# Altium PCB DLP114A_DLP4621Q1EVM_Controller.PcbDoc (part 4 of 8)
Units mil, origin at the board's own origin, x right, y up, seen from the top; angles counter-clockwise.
Board outline 4803.15 x 2598.43 mil, 14 copper layers (Top Layer, GND 1, SIGNAL 1, GND 2, SIGNAL 2, PWR SPLIT PLANE 1, GND 3, GND 4, PWR SPLIT PLANE 2, SIGNAL 3, GND 5, SIGNAL 4, GND 6, Bottom Layer), stack 91.4 mil thick; 489 components, 394 nets, 1925 pads, 1273 vias.
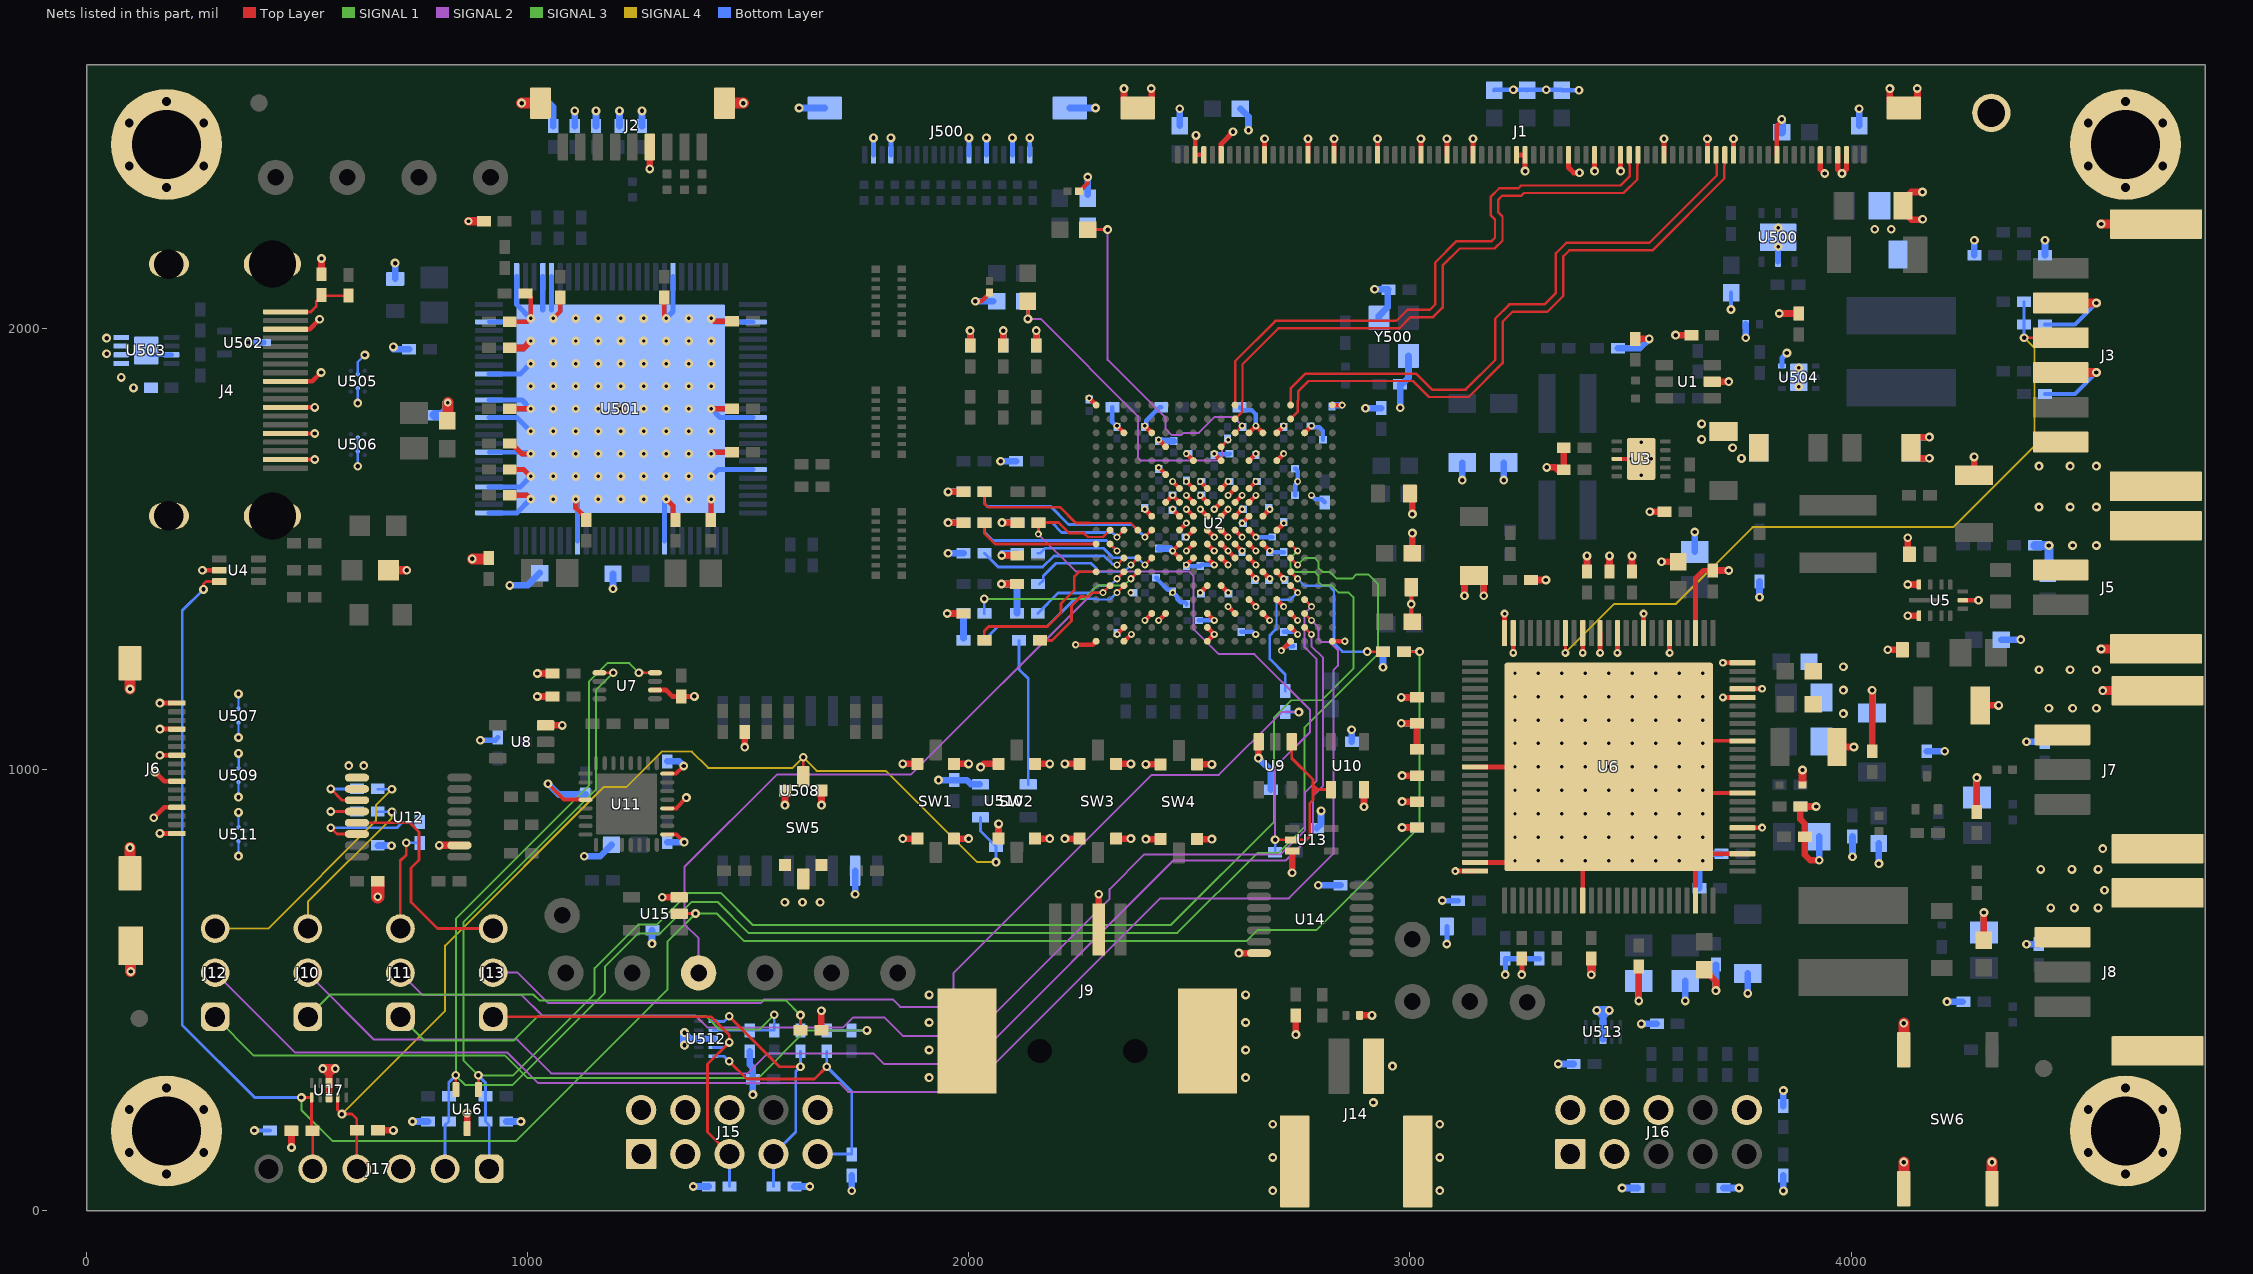
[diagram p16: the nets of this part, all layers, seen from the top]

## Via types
v1: diameter 20, hole 10, Top Layer to Bottom Layer, tented top, 716 vias
v2: diameter 16, hole 8, Top Layer to Bottom Layer, 234 vias
v3: diameter 19.68, hole 7.87, Top Layer to Bottom Layer, 170 vias
v4: diameter 18, hole 8, Top Layer to Bottom Layer, tented top, 78 vias
v5: diameter 18, hole 8, Top Layer to Bottom Layer, tented bottom, 51 vias
v6: diameter 39.37, hole 19.68, Top Layer to Bottom Layer, 24 vias

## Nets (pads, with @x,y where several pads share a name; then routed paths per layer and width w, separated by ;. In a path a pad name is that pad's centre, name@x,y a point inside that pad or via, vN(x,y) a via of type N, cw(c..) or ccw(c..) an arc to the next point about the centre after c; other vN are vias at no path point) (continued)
GND: C1.2 C2.2 C3.2 C6.2 C7.2 C8.2 C9.2 C10.2 C11.2 C12.2 C13.2 C14.2 C15.2 C16.2 C17.2 C18.2 C19.2 C20.2 C21.2 C22.2 C23.2 C24.1 C25.2 C27.2 C28.2 C29.2 C30.2 C31.1 C32.2 C33.2 C34.2 C35.1 C36.2 C37.1 C39.2 C40.2 C41.2 C42.2 C43.2 C44.2 C45.2 C46.2 C47.2 C48.2 C49.2 C50.2 C51.1 C52.2 C53.2 C54.2 C55.2 C56.1 C57.2 C58.2 C59.2 C500.2 C501.1 C502.2 C503.2 C504.2 C505.2 C506.2 C507.2 C508.2 C509.2 C510.2 C511.2 C512.2 C513.2 C514.2 C515.2 C516.2 C517.1 C518.2 C519.1 C520.2 C521.2 C522.2 C523.2 C524.2 C525.2 C526.2 C527.2 C528.2 C529.2 C530.2 C531.2 C532.2 C535.2 C536.2 C537.2 C538.2 C539.2 C540.2 C541.2 C542.2 C543.2 C544.2 C545.2 C546.2 C547.2 C548.2 C549.2 C550.2 C551.2 C552.2 C553.2 C554.2 C555.2 C556.2 C557.2 C558.2 C559.2 C560.2 C562.2 C563.2 C564.2 C565.2 C566.2 C567.2 C568.2 C569.2 C570.2 C571.2 C572.2 C573.2 C574.2 C575.2 C576.2 C577.2 C578.2 C579.2 C580.2 C581.2 C582.2 C583.2 C584.2 C585.2 C586.2 C587.2 C588.2 C589.2 C590.2 C591.2 C592.2 C593.2 C594.2 C595.2 C596.2 C597.2 C598.2 C599.2 C600.2 C601.2 C602.2 C603.2 C604.2 C605.2 C606.1 C607.2 C608.2 C609.2 C610.2 C612.1 C613.2 C614.2 C615.2 C616.2 C617.2 C618.2 C619.2 C620.2 C621.2 C622.2 C623.2 C624.2 C625.2 C626.2 C627.2 C628.2 D3.2 D5.2 J1.3 J1.4 J1.6 J1.11 J1.16 J1.19 J1.24 J1.29 J1.32 J1.35 J1.40 J1.41 J1.46 J1.49 J1.52 J1.57 J1.62 J1.65 J1.70 J1.75 J1.77 J1.78 J1.81 J1.82 J2.6 J2.10 J2.11 J3.1 J3.3 J3.5 J3.7 J3.8 J4.2 J4.5 J4.8 J4.11 J4.17 J4.20 J4.21 J4.22 J4.23 J5.2 J5.3 J5.4 J6.1 J6.4 J6.7 J6.10 J6.13 J6.16 J6.17 J6.18 J7.3 J7.MP1 J7.MP2 J8.3 J8.MP1 J8.MP2 J9.4 J9.5 J9.6 J14.2 J14.3 J14.4 J15.1 J15.2 J15.3 J15.4 J15.6 J15.10 J16.1 J16.2 J16.3 J16.4 J16.6 J16.10 J17.3 J500.2 J500.4 J500.13 J500.15 J500.18 J500.20 J500.21 J500.22 L513.1 L517.1 MH1.1 MH2.1 MH3.1 MH4.1 R3.1 R4.1 R5.1 R6.1 R7.1 R8.1 R13.1 R16.1 R18.1 R21.1 R22.1 R23.1 R26.1 R27.1 R28.1 R29.1 R30.1 R32.1 R33.1 R35.1 R40.1 R41.1 R47.1 R50.1 R52.1 R54.1 R61.1 R63.1 R65.1 R510.1 R511.1 R512.1 R514.1 R515.2 R525.1 R526.1 R527.1 R528.1 R529.1 R531.1 R533.1 R536.1 R537.1 R541.1 R542.1 R543.1 R544.1 R545.1 R547.1 R548.1 R550.1 R551.1 R559.1 R562.1 R565.1 R569.1 R573.1 R574.1 R575.1 R576.1 R578.1 R579.1 R584.1 R591.1 SW1.3 SW1.4 SW1.5 SW1.6 SW2.3 SW2.4 SW2.5 SW2.6 SW3.3 SW3.4 SW3.5 SW3.6 SW4.3 SW4.4 SW4.5 SW4.6 SW5.2 SW5.3 SW5.4 SW5.5 SW5.6 SW6.3 SW6.4 SW6.5 TP16.1 TP17.1 U1.2 U2.A1 U2.A18 U2.C3 U2.C5 U2.C12 U2.C13 U2.C14 U2.C16 U2.D6 U2.E8 U2.E10 U2.E12 U2.E14 U2.F6 U2.G7 U2.G8 U2.G9 U2.G10 U2.G11 U2.G12 U2.H6 U2.H7 U2.H8 U2.H9 U2.H10 U2.H11 U2.H12 U2.J5 U2.J7 U2.J8 U2.J9 U2.J10 U2.J11 U2.J12 U2.J13 U2.K7 U2.K8 U2.K9 U2.K10 U2.K11 U2.K12 U2.K14 U2.L7 U2.L8 U2.L9 U2.L10 U2.L11 U2.L12 U2.L13 U2.M7 U2.M8 U2.M9 U2.M10 U2.M11 U2.M12 U2.N12 U2.N13 U2.N14 U2.P9 U2.P10 U2.R12 U2.R14 U2.T5 U2.T6 U2.T9 U2.T11 U2.T13 U2.T15 U2.U3 U2.U9 U2.U15 U2.V1 U2.V3 U2.V9 U2.V15 U2.V18 U3.8 U3.11 U4.2 U5.1 U5.6 U5.11 U6.13 U6.24 U6.25 U6.35 U6.48 U6.53 U6.56 U6.60 U6.66 U6.71 U6.72 U6.75 U6.78 U6.81 U6.84 U6.87 U6.89 U6.91 U6.99 U6.100 U6.101 U7.2 U8.3 U9.3 U10.3 U11.4 U11.17 U11.20 U11.24 U12.2 U12.9 U12.10 U13.3 U14.7 U15.3 U16.3 U17.3@549.37,257.02 U17.8@549.37,289.89 U500.2 U500.7@3834.53,2206.85 U501.1 U501.4 U501.5 U501.19 U501.28 U501.39 U501.45 U501.58 U501.68 U501.76 U501.79 U501.83 U501.87 U501.89 U501.92 U501.98 U501.101 U502.3 U503.1 U503.2 U503.3 U503.4 U503.7 U503.9 U504.3 U504.7@3881.47,1889.67 U505.B1 U505.B2 U506.B1 U506.B2 U507.B1 U507.B2 U508.10 U509.B1 U509.B2 U510.3 U511.B1 U511.B2 U512.3@1420.73,389.93 U512.8@1387.86,389.93 U513.3@3437.55,388.98 U513.8@3437.55,421.85 Y500.2 Y500.4 | length 20175.6
  Top Layer w8: v3(3663.27,1059.47) 3669.18,1065.37 U6.66@3753.82,1065.37
  Top Layer w9: v1(1045.91,968.22) 1082.15,931.98 U11.4@1130.85,931.98 ; U11.17@1316.13,853.24 1336.95,853.24 v1(1354.41,835.78) ; U11.24@1316.13,991.03 1336.5,991.03 v1(1353.83,1008.36) ; U11.20@1316.31,912.3 1336.73,912.3 ; 1336.54,912.29 v1(1359.82,936.68) ; U3.8@3468.87,1704.49 v3(3501.35,1704.49) ; v3(3663.27,953.17) 3676.12,953.17 3682.03,947.26 U6.60@3753.82,947.26
  Top Layer w9.84: U5.6@4253.1,1384.35 v1(4288.81,1384.35)
  Top Layer w10: v1(262.46,1452.14) U4.2@300.88,1452.14 ; J4.2@451.18,1703.2 v1(517.36,1703.2) ; J4.5@451.18,1762.26 v1(517.36,1762.26) ; J4.8@451.18,1821.31 v1(517.36,1821.31) ; J4.11@451.18,1880.37 511.47,1880.37 v1(531.47,1900.37) ; J4.17@451.18,1998.48 505.65,1998.48 v1(528.18,2021.02) ; C11.2@959.35,2015.17 998.72,2015.17 v3(1006.59,2023.04) 1006.59,2071.86 998.91,2079.54 R3.1@994.97,2079.54 ; v3(1057.77,2023.04) 1073.52,2038.79 C7.2@1073.52,2070.28 ; C8.2@1309.74,2070.28 1309.74,2026.98 v3(1313.68,2023.04) ; v1(2014.75,2062.09) 2028.43,2062.09 2046.98,2080.64 C9.2@2046.98,2081.43 ; v2(2241.87,1283.28) 2280.68,1283.28 U2.V1@2288.57,1291.17 ; C1.2@2250.12,2311.38 2250.91,2311.38 2269.46,2329.93 v1(2269.46,2343.61) ; v2(2272.83,1842.35) U2.A1@2288.57,1826.6 ; v2(2335.82,1779.36) U2.C3@2351.57,1763.61 ; v2(2336.02,1306.9) 2336.02,1307.01 2351.57,1322.55 U2.U3@2351.57,1322.67 ; U2.V3@2351.57,1291.17 2352.34,1291.17 2367.73,1306.55 v2(2368.51,1306.55) ; v2(2398.81,1338.42) U2.T5@2414.56,1354.16 ; v2(2398.81,1590.38) U2.J5@2414.56,1574.64 ; v2(2398.81,1779.36) U2.C5@2414.56,1763.61 ; v2(2430.31,1338.42) U2.T6@2446.05,1354.16 ; v2(2430.31,1684.87) U2.F6@2446.05,1669.12 ; v2(2430.31,1747.86) U2.D6@2446.05,1732.12 ; U2.H6@2446.05,1606.13 v2(2461.8,1621.88) U2.H7@2477.55,1606.13 ; v2(2461.8,1590.38) U2.J7@2477.55,1574.64 ; v2(2461.8,1653.38) U2.G7@2477.55,1637.63 ; U2.M7@2477.55,1480.15 v2(2461.8,1495.9) U2.L7@2477.55,1511.64 ; U2.K7@2477.55,1543.14 v2(2493.3,1558.89) ; v2(2493.3,1464.4) U2.M8@2509.05,1480.15 ; v2(2493.3,1495.9) U2.L8@2509.05,1511.64 ; v2(2493.3,1527.39) U2.K8@2509.05,1543.14 ; v2(2493.3,1590.38) U2.J8@2509.05,1574.64 ; v2(2493.3,1621.88) U2.H8@2509.05,1606.13 ; v2(2493.3,1653.38) U2.G8@2509.05,1637.63 ; v2(2493.3,1716.37) U2.E8@2509.05,1700.62 ; J1.78@2512.91,2393.7 J1.77@2532.6,2393.7 ; J1.78@2513.25,2402.66 2513.25,2436.38 v1(2514.92,2438.05) ; v2(2524.79,1401.41) U2.P9@2540.54,1417.16 ; v2(2524.79,1590.38) U2.J9@2540.54,1574.64 ; v2(2524.79,1621.88) U2.H9@2540.54,1606.13 ; v2(2524.79,1653.38) U2.G9@2540.54,1637.63 ; U2.V9@2540.55,1291.17 v2(2556.29,1306.9) U2.U9@2540.54,1322.67 ; U2.T9@2540.54,1354.16 v2(2556.29,1338.42) ; U2.M9@2540.54,1480.15 v2(2556.29,1464.4) ; U2.L9@2540.54,1511.64 v2(2556.29,1495.9) ; U2.K9@2540.54,1543.14 v2(2556.29,1527.39) ; v2(2556.29,1590.38) U2.H10@2572.04,1606.13 ; v2(2556.29,1716.37) U2.E10@2572.04,1700.62 ; U2.P10@2572.04,1417.16 v2(2587.79,1401.41) ; U2.M10@2572.04,1480.15 v2(2587.79,1464.4) ; U2.L10@2572.04,1511.64 v2(2587.79,1495.9) U2.M11@2603.53,1480.15 ; U2.K10@2572.04,1543.14 v2(2587.79,1527.39) ; U2.J10@2572.04,1574.64 v2(2587.79,1590.38) ; U2.G10@2572.04,1637.63 v2(2587.79,1653.38) ; v2(2587.79,1369.91) U2.T11@2603.53,1354.16 ; v2(2587.79,1621.88) U2.G11@2603.53,1637.63 ; U2.L11@2603.53,1511.64 v2(2619.28,1495.9) ; U2.K11@2603.53,1543.14 v2(2619.28,1527.39) ; U2.J11@2603.53,1574.64 v2(2619.28,1590.38) ; U2.H11@2603.53,1606.13 v2(2619.28,1621.88) ; v2(2619.28,1558.89) U2.J12@2635.03,1574.64 ; U2.R12@2635.03,1385.66 v2(2650.78,1369.91) ; U2.N12@2635.03,1448.65 v2(2650.78,1432.9) ; U2.M12@2635.03,1480.15 v2(2650.78,1464.4) ; U2.L12@2635.03,1511.64 v2(2650.78,1495.9) ; U2.K12@2635.03,1543.14 v2(2650.78,1527.39) ; U2.H12@2635.03,1606.13 v2(2650.78,1621.88) ; U2.G12@2635.03,1637.63 v2(2650.78,1653.38) ; U2.E12@2635.03,1700.62 v2(2650.78,1716.37) ; U2.C12@2635.03,1763.61 v2(2650.78,1779.36) U2.C13@2666.53,1763.61 ; U2.T13@2666.53,1354.16 2666.53,1353.93 2681.81,1338.65 v2(2681.81,1338.42) ; U2.N13@2666.53,1448.65 v2(2682.27,1432.9) ; U2.L13@2666.53,1511.64 v2(2682.27,1495.9) ; U2.J13@2666.53,1574.64 v2(2682.27,1590.38) ; U2.R14@2698.02,1385.66 v2(2713.77,1369.91) ; U2.N14@2698.02,1448.65 v2(2713.77,1432.9) ; U2.K14@2698.02,1543.14 v2(2713.77,1558.89) ; U2.E14@2698.02,1700.62 v2(2713.77,1716.37) ; U2.C14@2698.02,1763.61 v2(2713.77,1779.36) ; v2(2708.31,1269.96) U2.V15@2729.52,1291.17 ; U2.U15@2729.52,1322.67 v2(2745.27,1306.9) ; U2.T15@2729.52,1354.16 v2(2745.27,1338.42) ; U2.C16@2761.01,1763.61 v2(2776.76,1779.36) ; U2.A18@2824.01,1826.6 v2(2846.28,1826.6) ; U2.V18@2824.19,1291.17 v2(2852.54,1291.17) ; C35.1@3002.89,1413.65 v1(3002.89,1375.52) 3002.89,1337.38 C36.2@3005.35,1334.92 ; J1.11@3831.81,2393.7 3831.81,2460.49 3842.7,2471.38 v1(3842.7,2474.09)
  Top Layer w11: v1(152.34,891.13) 175.99,914.77 J6.13@204.72,914.77 ; v1(155.29,994.54) 176,973.83 J6.10@204.72,973.83 ; v1(166.04,855.72) J6.16@204.72,855.72 ; v1(166.04,1032.88) J6.7@204.72,1032.88 ; v1(166.04,1091.94) J6.4@204.72,1091.94 ; v1(166.04,1150.99) J6.1@204.72,1150.99 ; U7.2@1288.48,1180.54 1313.62,1180.54 1328.07,1166.09 C40.2@1348.1,1166.09 v1(1377.91,1166.09) ; v4(3103,770.1) U6.25@3147.52,770.1 ; U6.24@3147.52,789.78 3234.38,789.78 U6.101@3237.78,793.19 ; U6.13@3147.52,1006.32 v3(3238.08,1006.32) ; U6.100@3214.45,1309.47 v4(3214.45,1354) ; v4(3234.14,1264.94) U6.99@3234.14,1309.47 ; J1.41@3241.26,2393.7 J1.40@3260.94,2393.7 ; v3(3344.37,793.72) 3373.5,793.72 3391.62,775.6 U6.35@3391.62,703.17 ; v4(3391.62,1264.94) U6.91@3391.62,1309.47 ; v4(3430.99,1264.94) U6.89@3430.99,1309.47 ; v4(3470.36,1264.94) U6.87@3470.36,1309.47 ; U6.84@3529.41,1309.47 v4(3529.41,1354) ; v4(3588.47,1264.94) U6.81@3588.47,1309.47 ; U6.48@3647.52,703.17 3647.52,777.97 v3(3663.27,793.72) ; U6.101@3647.52,809.47 U6.53@3753.82,809.47 ; v4(3709.3,1163.8) U6.71@3753.82,1163.8 ; v4(3709.3,1242.54) U6.75@3753.82,1242.54 ; U6.56@3753.82,868.52 v4(3798.35,868.52) ; U6.72@3753.82,1183.48 v4(3798.35,1183.48)
  Top Layer w11.8: J1.75@2571.97,2393.7 2571.97,2418.76 2598.78,2445.56 v1(2598.78,2446.37) ; J1.70@2670.39,2393.7 v1(2670.39,2430.39) ; J1.65@2768.82,2393.7 v1(2768.82,2430.39) ; J1.62@2827.87,2393.7 v1(2827.87,2430.39) ; J1.57@2926.3,2393.7 v1(2926.3,2430.39) ; J1.52@3024.72,2393.7 v1(3024.72,2430.39) ; J1.49@3083.78,2393.7 v1(3083.78,2430.39) ; J1.46@3142.83,2393.7 v1(3142.83,2430.39) ; v1(3260.94,2357.02) J1.40@3260.94,2393.7 ; J1.35@3359.37,2393.7 3359.38,2364.94 3371.14,2353.18 v1(3384.31,2353.18) ; v1(3418.43,2357.02) J1.32@3418.43,2393.7 ; v1(3477.48,2357.02) J1.29@3477.48,2393.7 ; J1.24@3575.91,2393.7 v1(3575.91,2430.39) ; J1.19@3674.33,2393.7 v1(3674.33,2430.39) ; J1.16@3733.39,2393.7 v1(3733.39,2430.39) ; J1.6@3930.24,2393.7 3930.24,2361.41 v1(3940.08,2351.57) ; J1.4@3969.61,2393.7 3969.61,2361.41 v1(3979.45,2351.57) 3989.29,2361.41 J1.3@3989.29,2393.7
  Top Layer w11.81: C16.2@817.87,1790.87 C16.2@818.75,1791.74 ; C25.2@959.35,1622.06 998.13,1622.06 v3(1006.59,1613.59) ; C22.2@959.35,1680.52 990.84,1680.52 v3(1006.59,1664.77) ; C20.2@959.35,1739.58 963.28,1739.58 986.91,1715.95 v3(1006.59,1715.95) ; C14.2@959.35,1818.32 v3(1006.59,1818.32) ; v3(1108.95,1613.59) 1108.95,1593.91 1132.58,1570.28 C28.2@1132.58,1566.35 ; v3(1313.68,1613.59) 1329.03,1598.24 1329.03,1572.25 C29.2@1334.94,1566.35 ; C30.2@1414.94,1566.35 1415.49,1566.9 1415.49,1613.04 v3(1416.04,1613.59) ; v3(1416.04,1715.95) 1419.98,1719.89 C21.2@1463.28,1719.89 ; v3(1416.04,1818.32) C15.2@1463.28,1818.32 ; v3(1416.04,2023.04) 1422.67,2016.41 C10.2@1463.28,2016.41 ; v1@3253.82,535.43 R61.1@3253.82,571.67 ; U6.78@3647.52,1309.47 3647.52,1433.85 3665.17,1451.5 R27.1@3686.78,1451.5
  Top Layer w15: v1(464.5,143.61) C58.2@464.5,181.81 ; C6.2@532.56,2123.12 v1(532.56,2158.87) ; v1(535.23,322.45) 549.37,308.31 ; U17.3@549.37,257.02 U17.8@549.37,289.89 549.37,308.31 ; v1(563.51,322.45) 549.37,308.31 ; C57.2@660.14,182.29 v1(695.35,182.29) ; U16.3@862.58,186.35 v1(862.58,222.09) ; C13.2@959.35,1956.11 990.84,1956.11 v3(1006.59,1971.86) ; v1(1022.05,1166) C42.2@1056.56,1166 ; v1(1022.05,1218.07) R40.1@1056.56,1218.07 ; U8.3@1040.44,1100.52 v1(1078.12,1100.52) ; v1(1276.69,2362.1) J2.6@1276.69,2411.61 ; v1(1304.75,710.73) U15.3@1343.44,710.73 ; v1(1492.05,1051.14) C44.2@1492.05,1085.89 ; v1(1583.19,919.77) SW5.3@1583.19,953.17 ; R65.1@1665.65,409.02 v1(1665.65,453.77) ; v1(1665.87,919.77) SW5.4@1665.87,953.17 ; v1(1850.04,843.88) SW1.5@1883.44,843.88 ; v1(1850.04,1013.17) SW1.3@1883.44,1013.17 ; v1(1951.03,1354.08) R35.1@1987.78,1354.08 ; v1(1953.03,1560.13) R22.1@1987.78,1560.12 ; v1(1953.03,1629.74) R18.1@1987.78,1629.72 ; SW1.6@1966.12,843.88 v1(1999.52,843.88) ; SW1.4@1966.12,1013.17 v1(1999.52,1013.17) ; R6.1@2002.79,1961.56 v1(2002.79,1995.31) ; v1(2026.65,1005.9) 2033.93,1013.17 SW2.3@2067.33,1013.17 ; SW2.5@2067.33,843.88 v1(2067.33,877.28) ; v1(2073.98,1420.91) R33.1@2109.18,1420.91 ; v1(2074.61,1485.52) R26.1@2109.82,1485.52 ; v1(2075.12,1560.12) R23.1@2110.32,1560.12 ; R7.1@2077.78,1961.56 v1(2077.78,1995.31) ; SW2.6@2150,843.88 v1(2183.4,843.88) ; SW2.4@2150,1013.17 v1@2183.44,1013.21 ; R8.1@2152.78,1961.56 v1(2152.78,1995.31) ; v1(2217.81,843.88) SW3.5@2251.21,843.88 ; v1(2217.81,1013.17) SW3.3@2251.21,1013.17 ; J9.4@2294.3,637.8 v1(2294.3,717.63) ; SW3.6@2333.89,843.88 v1(2367.29,843.88) ; SW3.4@2333.89,1013.17 v1(2367.29,1013.17) ; v1(2351.66,2543.93) 2351.66,2518.21 2369.87,2500 J1.82@2382.99,2500 2396.11,2500 2414.33,2518.21 v1@2414.33,2543.93 ; v1(2401.35,1011.99) SW4.3@2434.75,1011.99 ; v1@2401.39,842.73 SW4.5@2434.72,842.73 ; SW4.6@2517.46,842.73 v1@2550.79,842.73 ; SW4.4@2517.43,1011.99 v1(2550.83,1011.99) ; v1(2612.12,584.35) U14.7@2657.68,584.35 ; v1(2656.39,1026.31) U9.3@2656.39,1065 ; 2732.9,776.59 U13.3@2732.9,815.47 ; v1(2741.35,399.57) R63.1@2741.35,443.16 ; C56.1@2886,442.96 v1(2913.89,442.96) ; v1(2895.75,916.15) U10.3@2895.75,954.84 ; v1(2980.19,1163.8) R41.1@3015.63,1163.8 ; v1@2980.33,1105.33 3015.49,1105.33 R47.1@3015.63,1105.2 R50.1@3015.63,1046.6 ; v1(2982.16,868.98) R54.1@3015.63,868.98 ; v1(2982.16,927.58) R52.1@3015.63,927.58 ; v1(2982.16,986.63) C47.2@3015.63,986.63 ; C24.1@2999.94,1626.13 3005.35,1620.72 v1(3005.35,1579.53) ; C32.2@3005.35,1491.04 v1(3005.35,1536.42) ; v1(3123.66,1394.17) 3123.66,1426.39 3137.82,1440.54 C27.2@3145.36,1440.54 3152.9,1440.54 3167.05,1426.39 v1(3167.05,1394.17) ; R32.1@3274.28,1430.14 v1(3308.03,1430.14) ; v1(3310.11,1685.24) 3329.06,1685.24 3334.43,1679.87 R16.1@3348.59,1679.87 R13.1@3348.59,1729.87 ; R28.1@3401.3,1449.02 v1(3401.3,1484.77) ; v3(3450.67,1006.32) v3(3503.82,953.17) v3(3556.97,900.02) v3(3610.12,846.87) U6.101@3647.52,809.47 ; R29.1@3452.3,1449.02 v1(3452.3,1484.77) ; R30.1@3503.3,1449.02 v1(3503.3,1484.77) ; C12.2@3510.7,1976.7 v1(3542.51,1976.7) ; v1(3518.58,475.87) C55.2@3518.58,554.15 ; v1(3543.95,1584.74) R21.1@3576.87,1584.74 ; v1(3570.11,1471.35) C34.2@3607.86,1471.35 ; v1(3602.08,1985.18) R5.1@3637.83,1985.18 ; C54.2@3667.21,546.81 3693.57,520.45 v1(3693.57,499.3) ; U1.2@3685.07,1879.79 v1(3722.76,1879.79) ; R27.1@3686.78,1451.5 v1(3722.53,1451.5) ; v1(3837.16,2034.17) R4.1@3881.47,2034.17 ; v1(3920.78,916.58) C48.2@3885.03,916.58 3885.03,887.61 3895.06,877.58 C50.2@3895.06,848.22 3895.06,807.09 3907.55,794.59 v1(3927.81,794.59) ; C45.2@3968.44,1051.58 v1(4006.32,1051.58) ; C46.2@4047.58,1041.75 v1(4047.58,1180.08) ; v1(4082.88,1272.09) C37.1@4116.07,1272.09 ; v1(4087.88,2543.93) 4087.88,2518.21 4106.09,2500 J1.81@4119.21,2500 4132.33,2500 4150.55,2518.21 v1@4150.55,2543.93 ; v1(4128.27,1348.92) U5.1@4150.96,1348.92 ; v1(4128.27,1419.79) U5.11@4150.96,1419.79 ; v1(4128.27,1525.88) 4128.27,1491.9 C31.1@4132.01,1488.16 ; v1@4161.89,2246.97 4136.17,2246.97 4117.96,2265.19 C2.2@4117.96,2278.31 4117.96,2291.43 4136.17,2309.64 v1(4161.89,2309.64) ; v1(4177.38,1705.87) 4146.13,1705.87 4135.7,1716.31 C19.2@4135.7,1729.87 4135.7,1743.44 4146.13,1753.87 v1(4177.38,1753.87) ; C23.2@4278.78,1667.46 v1(4278.78,1709.15) ; C49.2@4285.15,903.86 v1(4285.15,982.16) ; C41.2@4292.72,1145.81 v1(4334.41,1145.81) ; C53.2@4301.12,613.73 v1(4301.12,676.28)
  Top Layer w17: v1(799.5,828.47) U12.2@845.06,828.47
  Top Layer w18.8: D5.2@3889.76,967.37 v1(3889.76,999.27)
  Top Layer w20: v1@535.51,322.45 v1(563.51,322.45) ; D3.2@684.14,1452.12 v1(725.79,1452.12) ; v5(865.74,2243.36) C3.2@900.49,2243.36 ; v1@3411.3,535.23 C52.2@3411.3,571.67 ; J3.3@4475.2,1900.43 v1(4556.19,1900.43) ; J3.5@4475.2,2057.91 v1(4556.19,2057.91) ; v1(4566.61,1273.74) J5.3@4690.94,1273.74 ; v1(4566.61,2237.04) J3.8@4690.94,2237.04 ; v1(4570.55,1179.37) J7.MP2@4694.88,1179.37
  Top Layer w25: J6.18@98.43,765.17 v1(98.43,823.54) ; v1(98.43,1182.94) J6.17@98.43,1241.55 ; v1@99.95,542.49 TP16.1@99.95,600.86 ; C16.2@818.75,1791.74 v5(818.75,1831.97) ; v1(874.3,1477.94) C33.2@910.28,1477.94 ; v1(986.03,2511.02) J2.11@1028.66,2511.02 ; J2.10@1445.98,2511.02 v1(1488.6,2511.02) ; SW6.4@4119.39,50.22 v1(4119.39,110.38) ; SW6.3@4119.39,365.19 v1(4119.39,425.34) ; SW6.5@4319.39,50.22 v1(4319.39,110.38)
  Top Layer w30: v1(660.02,711.98) C51.1@660.02,743.41
  Bottom Layer w5.5: v1(344.42,804.23) U511.B2@344.42,837.97 ; U511.B1@344.42,869.47 v1(344.42,903.22) ; v1(344.42,937.94) U509.B2@344.42,971.69 ; U509.B1@344.42,1003.19 v1(344.42,1036.94) ; v1(344.42,1072.95) U507.B2@344.42,1106.7 ; U507.B1@344.42,1138.19 v1(344.42,1171.94) ; v1(614.77,1687.77) U506.B2@614.77,1721.52 U506.B1@614.77,1753.02 ; v1(614.77,1831.19) U505.B2@614.77,1864.93 ; U505.B1@614.77,1896.43 614.77,1924.05 v1(630.82,1940.09)
  Bottom Layer w10: U503.9@135.48,1950.36 145.32,1940.52 U503.7@192.57,1940.52 ; v1(380.45,182.03) C622.2@415.51,182.03 ; U501.83@912.1,1719.89 1002.65,1719.89 v3(1006.59,1715.95) ; U501.98@912.1,2015.17 U501.101@979.56,2015.17 ; R528.1@2325.21,1821.42 2325.21,1788 2333.85,1779.36 v2(2335.82,1779.36) ; v2(2398.81,1779.36) 2400.78,1779.36 2402.08,1780.66 2402.08,1791.31 2432.18,1821.42 R527.1@2436.12,1821.42 ; C574.2@2424.79,1435 2425.58,1435 2428.85,1431.74 2428.85,1429.86 2450.88,1407.83 2458.3,1407.83 2461.57,1404.56 C578.2@2461.57,1403.77 2461.57,1402.99 2472.61,1391.94 2472.61,1387.25 2480.39,1379.48 2490.03,1379.48 2493.3,1376.21 C579.2@2493.3,1375.42 ; v2(2493.3,1464.4) 2496.05,1461.64 C569.2@2524.79,1461.64 2527.55,1464.4 v2(2556.29,1464.4) ; C585.2@2521.28,1338.42 v2(2556.29,1338.42) ; v2(2556.29,1716.37) 2557.67,1714.99 2589.82,1714.99 C542.2@2591.2,1716.37 ; R526.1@2613.53,1821.42 2620.41,1814.54 2641.74,1814.54 2650.78,1805.5 v2(2650.78,1779.36) ; C583.2@2617.18,1312.62 2642.99,1312.62 2648.69,1306.92 v2(2650.32,1306.92) ; v2(2650.78,1527.39) C563.2@2687.79,1527.39 ; C568.2@2679.83,1496.24 2682.92,1493.14 C567.2@2713.77,1493.14 ; v2(2708.31,1269.96) 2717.87,1279.52 C588.2@2735.03,1279.52 ; C584.2@2713.77,1312.43 2739.75,1312.43 v2(2745.27,1306.9) ; C552.2@2739.75,1621.88 2739.75,1646.24 2745.27,1651.75 v2(2745.27,1653.38) 2745.27,1676.6 2743.81,1678.06 2743.81,1678.85 2740.54,1682.12 C547.2@2739.75,1682.12 ; v2(2776.76,1621.88) 2785.62,1613.02 2799.76,1613.02 2806.57,1606.21 R531.1@2806.57,1606.13 ; v2(2776.76,1779.36) 2776.76,1777.39 2778.06,1776.09 2794.74,1776.09 2802.75,1768.08 C538.2@2802.75,1747.86 ; C502.2@3191.13,2540.41 3192.07,2541.35 v1(3234.35,2541.35) 3264.69,2541.35 C503.2@3265.63,2540.41 3266.57,2541.35 v1(3308.85,2541.35) 3343.44,2541.35 C501.1@3344.38,2540.41 v1(3383.08,2540.41) ; v1(3727.75,2043.18) C516.2@3727.75,2080.86 ; C523.2@4439.45,1851.69 4507.45,1851.69 v1(4556.19,1900.43) ; C520.2@4439.45,2009.17 4507.45,2009.17 v1(4556.19,2057.91)
  Bottom Layer w11: J500.2@1783.77,2393.7 v1(1783.77,2432.39) ; J500.4@1823.14,2393.7 v1(1823.14,2432.39) ; J500.13@2000.31,2393.7 v1(2000.31,2432.39) ; J500.15@2039.68,2393.7 v1(2039.68,2432.39) ; J500.18@2098.74,2393.7 v1(2098.74,2432.39) ; J500.20@2138.11,2393.7 v1(2138.11,2432.39)
  Bottom Layer w11.81: v1(892.65,1066.98) 926.27,1066.98 C593.2@932.17,1072.88 ; U501.76@912.1,1582.1 975.09,1582.1 v3(1006.59,1613.59) ; U501.79@912.1,1641.15 982.97,1641.15 v3(1006.59,1664.77) ; U501.87@912.1,1798.63 975.09,1798.63 v3(1006.59,1767.13) ; U501.89@912.1,1838 986.91,1838 v3(1006.59,1818.32) ; U501.92@912.1,1897.06 982.97,1897.06 v3(1006.59,1920.68) ; U501.1@975.09,2117.53 975.09,2054.54 v3(1006.59,2023.04) ; U501.101@1034.15,2042.32 U501.4@1034.15,2117.53 ; U501.101@1053.84,2042.32 U501.5@1053.84,2117.53 ; v3(1108.95,1613.59) 1112.89,1609.65 U501.68@1112.89,1519.1 ; U501.58@1309.74,1519.1 1309.74,1609.65 v3(1313.68,1613.59) ; v3(1313.68,2023.04) 1329.43,2038.79 U501.19@1329.43,2117.53 ; v3(1416.04,1664.77) 1431.79,1680.52 U501.45@1510.53,1680.52 ; v3(1416.04,1818.32) 1435.72,1798.63 U501.39@1510.53,1798.63 ; v3(1416.04,2023.04) 1423.91,2015.17 U501.28@1510.53,2015.17 ; v1@3073.05,703.17 C609.2@3109.29,703.17 ; v1@3083.7,604.92 C612.1@3083.7,644.59 ; v1@3216.44,535.43 R575.1@3216.44,571.67 R574.1@3293.19,571.67 ; U504.3@3843.08,1915.26 3843.08,1933.17 v1(3854.57,1944.65)
  Bottom Layer w13.78: U500.2@3834.53,2151.73 v3(3834.53,2185.2)
  Bottom Layer w14: v1(366.95,1968.44) U502.3@400.99,1968.44
  Bottom Layer w15: C606.1@660.66,827.83 660.92,828.1 v1@690.79,828.1 ; v1@695.47,1953.52 R515.2@731.22,1953.52 ; C517.1@699.43,2112.67 v1(699.43,2148.42) ; v1(738.81,202.58) C621.2@773.86,202.58 ; C620.2@951.3,202.58 v1(984.38,202.58) ; v1(959.15,1417.93) 999.55,1417.93 C572.2@1027.42,1445.8 ; v1(986.03,2511.02) 1048.54,2511.02 1058.12,2501.45 C510.2@1058.12,2458.86 ; v1(1045.91,968.22) 1070.35,943.79 C597.2@1130.85,943.79 ; C509.2@1106.42,2458.86 v1(1106.42,2493.61) ; v1(1128.11,803.99) 1164.51,803.99 C605.2@1190.02,829.5 ; C508.2@1154.73,2458.86 v1(1154.73,2493.61) ; v1(1193.28,1410.38) C573.2@1193.28,1444.08 ; C507.2@1208.04,2458.86 v1(1208.04,2493.61) ; C506.2@1259.04,2458.86 v1(1259.04,2493.61) ; v1(1281.66,605.79) C614.2@1281.66,635.93 ; C603.2@1316.13,835.78 v1(1354.41,835.78) ; C596.2@1316.7,1019.16 1343.03,1019.16 v1(1353.83,1008.36) ; v1(1355.3,375.78) 1369.44,389.93 ; v1(1355.3,404.07) 1369.44,389.93 ; v1(1375.19,55.12) C626.2@1410.24,55.12 ; U512.3@1420.73,389.93 U512.8@1387.86,389.93 1369.44,389.93 ; R584.1@1502.9,361.77 1502.9,332.13 1510.53,324.5 C618.2@1510.53,298.56 v1(1510.53,263.51) ; C625.2@1604.34,55.12 v1(1639.39,55.12) ; v1(1615.17,2500) J500.21@1673.54,2500 ; v1(1734.71,45.47) C623.2@1734.71,80.52 ; v1(1742.05,717.48) U508.10@1742.05,770.93 ; v1(1931.24,976.52) C598.2@1966.45,976.52 1995.03,976.52 2004.2,967.35 U510.3@2024.47,967.35 ; v1(1951.03,1354.08) R547.1@1987.78,1354.08 ; v1(1953.03,1490.52) R543.1@1987.78,1490.52 ; v1(1953.03,1560.13) R537.1@1987.78,1560.12 R537.1@1992.78,1560.12 ; v1(1953.03,1629.74) R533.1@1987.78,1629.72 ; R550.1@1987.78,1298.01 R547.1@1987.78,1354.08 ; R547.1@1987.78,1354.31 R547.1@1987.78,1354.08 ; R547.1@1988.23,1354.08 R547.1@1987.78,1354.08 ; R512.1@2002.79,1961.56 v1(2002.79,1995.31) ; v1(2014.75,2062.09) L517.1@2055.2,2062.09 ; v1(2071.96,1699.32) R529.1@2107.17,1699.32 ; v1(2073.98,1420.91) R545.1@2109.18,1420.91 R548.1@2109.18,1354.61 ; v1@2074.61,1490.52 R542.1@2109.82,1490.52 ; v1(2075.12,1560.12) R536.1@2110.32,1560.12 ; R511.1@2077.78,1961.56 v1(2077.78,1995.31) ; R510.1@2152.78,1961.56 v1(2152.78,1995.31) ; J500.22@2228.66,2500 v1(2287.03,2500) ; L513.1@2269.46,2303.16 v1(2269.46,2343.61) ; C562.2@2430.31,1501.41 2456.29,1501.41 v2(2461.8,1495.9) ; v2(2430.31,1747.86) 2433.06,1745.11 C539.2@2464.56,1745.11 ; C504.2@2478.04,2459.72 v1(2478.04,2498.42) ; C500.2@2615.28,2498.69 2633.88,2480.09 v1(2633.88,2449.52) ; v1(2656.39,1026.31) 2684.61,998.09 C599.2@2684.61,954.84 ; C59.2@2788.85,867.52 2798.41,877.08 v1(2798.41,906.6) ; v1(2792.17,737.89) C608.2@2842.72,737.89 ; C527.2@2823.35,1823.85 2826.11,1826.6 v2(2846.28,1826.6) ; v1(2867.57,1090.72) 2867.57,1063.73 C595.2@2868.19,1063.11 ; v1(2899.23,1819.58) R525.1@2935.04,1819.58 ; v1@2919.7,2088.88 C518.2@2950.82,2088.88 ; Y500.4@2929.59,2024.57 2929.59,2028.5 2949.27,2048.19 C518.2@2949.27,2088.43 ; v1(2938.75,1232.15) R551.1@2938.75,1267.65 ; v1@2977.81,1824.54 C521.2@2977.81,1873.66 2981.74,1873.66 2996.52,1888.43 Y500.2@2996.52,1937.95 ; v1@2980.19,868.98 v1(2982.16,868.98) R569.1@3015.63,868.98 ; v1@2980.33,1105.33 3015.49,1105.33 R559.1@3015.63,1105.2 ; v1(3118.67,1656.41) C525.2@3118.67,1696.06 ; C559.2@3145.36,1440.54 3152.9,1440.54 3167.05,1426.39 v1(3167.05,1394.17) ; v1(3212.41,1656.41) C526.2@3212.41,1696.06 ; v1(3336.09,332.78) R591.1@3371.14,332.78 ; v1(3423.41,454.41) 3437.55,440.27 ; U513.3@3437.55,388.98 U513.8@3437.55,421.85 3437.55,440.27 ; v1(3451.69,454.41) 3437.55,440.27 ; R514.1@3471.24,1955.24 3521.05,1955.24 v1(3542.51,1976.7) ; v1(3480.91,51.75) C628.2@3515.96,51.75 ; v1(3518.58,475.87) C615.2@3518.58,521.39 ; v1(3524.5,423.69) R579.1@3559.56,423.69 ; v1(3624.03,475.81) C616.2@3624.03,521.33 ; C565.2@3645.48,1493.87 v1(3645.48,1538.87) ; R573.1@3655.94,731.41 3655.94,786.39 v3(3663.27,793.72) 3679.34,809.78 C607.2@3706.58,809.78 ; v1(3693.57,499.3) v1(3693.57,499.3) R576.1@3693.62,558.23 ; C627.2@3710.78,51.75 v1(3745.83,51.75) ; v1(3761.13,1979.37) C519.1@3761.13,2010.04 ; v1(3765.66,492.88) C610.2@3765.66,538.4 ; v1(3792.3,1390.89) R544.1@3792.3,1426.63 ; v1(3846.49,45.14) C624.2@3846.49,80.2 ; C619.2@3846.59,237.65 v1(3846.59,272.7) ; R565.1@3885.03,916.58 v1(3920.78,916.58) ; v1(3927.81,794.59) C604.2@3927.81,848.22 C604.2@3928.18,848.58 ; v1(4003.07,802.77) C602.2@4003.07,848.58 ; C505.2@4018.17,2459.72 v1(4018.17,2498.42) ; C591.2@4047.58,1128.36 v1(4047.58,1180.08) ; v1(4063.07,787.03) C601.2@4063.07,832.84 ; R562.1@4171.7,1041.75 v1(4212.2,1041.75) ; v1(4177.38,1705.87) 4146.13,1705.87 4135.7,1716.31 C537.2@4135.7,1729.87 4135.7,1743.44 4146.13,1753.87 v1(4177.38,1753.87) ; v1(4217.44,474.26) R578.1@4252.5,474.26 ; C515.2@4279.4,2166.47 v1(4279.4,2200.22) ; C600.2@4285.15,936.61 v1(4285.15,982.16) ; C613.2@4301.12,630.74 v1(4301.12,676.28) ; C587.2@4340.71,1295.01 v1(4384.46,1295.01) ; v1(4397.64,604.52) C617.2@4425.13,604.52 ; v1(4397.64,1063.23) C594.2@4439.13,1063.23 ; C514.2@4439.45,2166.65 v1(4439.45,2200.4)
  Bottom Layer w20: v1@1355.3,376.07 v1(1355.3,404.07) ; v1@3423.69,454.41 v1(3451.69,454.41) ; C511.2@3842.7,2445.39 v1(3842.7,2474.09) ; R541.1@4416.56,1508.36 4448.42,1508.36 v1(4448.46,1508.33) 4448.46,1447.62 C571.2@4445.83,1445
  Bottom Layer w23: C528.2@789.2,1803.79 806.36,1803.79 818.75,1816.18 v5(818.75,1831.97)
  other v1: 2688.93,45.83 3067.31,45.83 2688.93,120.97 3067.31,120.97 2688.93,196.12 3067.31,196.12 2917.02,245.64 1909.99,302.15 2627.42,302.15 2960.35,328.22 1909.99,364.58 2627.42,364.58 1909.99,427 2627.42,427 1909.99,489.43 2627.42,489.43 3216.16,535.43 3253.54,535.43 3411.02,535.23 99.95,542.49 3083.42,604.92 4452.4,686.87 4506.14,686.87 4559.87,686.87 1582.97,699.42 1622.84,699.42 1662.71,699.42 3073.05,703.45 4574.49,726.73 2732.9,766.59 4429.95,774.14 4500.44,774.14 4559.87,774.14 4570.55,821.1 691.16,827.72 2401.35,842.77 2550.83,842.77 594.35,1009.25 628.24,1009.25 2183.48,1013.25 2980.19,1105.47 3982.43,1127.27 4448.46,1139.51 4502.2,1139.51 4555.94,1139.51 3982.43,1180.33 4426.01,1226.78 4496.5,1226.78 4555.94,1226.78 3982.43,1233.4 4502.2,1508.33 4555.94,1508.33 4426.01,1595.6 4496.5,1595.6 4555.94,1595.6 4426.01,1688.26 4496.5,1688.26 4555.94,1688.26 3751.6,1705.81 3731.31,1730.06 3661.14,1748.86 3661.14,1783.86 2977.81,1820.54 106.37,1865.47 78.39,1889.26 45.34,1943.09 695.47,1958.52 45.34,1978.54 2919.7,2089.34 4053.48,2225.38 4091.15,2225.38 4162.12,2247.68 2413.62,2544.17 4149.84,2544.17
  other v2: 2367.31,1401.41 2461.8,1401.41
  other v3: 3238.08,793.72 3291.22,793.72 3397.52,793.72 3450.67,793.72 3503.82,793.72 3556.97,793.72 3610.12,793.72 3238.08,846.87 3291.22,846.87 3344.37,846.87 3397.52,846.87 3450.67,846.87 3503.82,846.87 3556.97,846.87 3663.27,846.87 3238.08,900.02 3291.22,900.02 3344.37,900.02 3397.52,900.02 3450.67,900.02 3503.82,900.02 3610.12,900.02 3663.27,900.02 3238.08,953.17 3291.22,953.17 3344.37,953.17 3397.52,953.17 3450.67,953.17 3556.97,953.17 3610.12,953.17 3291.22,1006.32 3344.37,1006.32 3397.52,1006.32 3503.82,1006.32 3556.97,1006.32 3610.12,1006.32 3663.27,1006.32 3238.08,1059.47 3291.22,1059.47 3344.37,1059.47 3397.52,1059.47 3450.67,1059.47 3503.82,1059.47 3556.97,1059.47 3610.12,1059.47 3238.08,1112.62 3291.22,1112.62 3344.37,1112.62 3397.52,1112.62 3450.67,1112.62 3503.82,1112.62 3556.97,1112.62 3610.12,1112.62 3663.27,1112.62 3238.08,1165.77 3291.22,1165.77 3344.37,1165.77 3397.52,1165.77 3450.67,1165.77 3503.82,1165.77 3556.97,1165.77 3610.12,1165.77 3663.27,1165.77 3238.08,1218.92 3291.22,1218.92 3344.37,1218.92 3397.52,1218.92 3450.67,1218.92 3503.82,1218.92 3556.97,1218.92 3610.12,1218.92 3663.27,1218.92 1057.77,1613.59 1160.13,1613.59 1211.32,1613.59 1262.5,1613.59 1364.86,1613.59 1057.77,1664.77 1108.95,1664.77 1160.13,1664.77 1211.32,1664.77 1262.5,1664.77 1313.68,1664.77 1364.86,1664.77 3523.99,1667.09 3546.63,1704.49 1057.77,1715.95 1108.95,1715.95 1160.13,1715.95 1211.32,1715.95 1262.5,1715.95 1313.68,1715.95 1364.86,1715.95 3523.99,1741.89 1057.77,1767.13 1108.95,1767.13 1160.13,1767.13 1211.32,1767.13 1262.5,1767.13 1313.68,1767.13 1364.86,1767.13 1416.04,1767.13 1057.77,1818.32 1108.95,1818.32 1160.13,1818.32 1211.32,1818.32 1262.5,1818.32 1313.68,1818.32 1364.86,1818.32 3881.47,1868.01 1006.59,1869.5 1057.77,1869.5 1108.95,1869.5 1160.13,1869.5 1211.32,1869.5 1262.5,1869.5 1313.68,1869.5 1364.86,1869.5 1416.04,1869.5 3881.47,1911.32 1057.77,1920.68 1108.95,1920.68 1160.13,1920.68 1211.32,1920.68 1262.5,1920.68 1313.68,1920.68 1364.86,1920.68 1416.04,1920.68 1057.77,1971.86 1108.95,1971.86 1160.13,1971.86 1211.32,1971.86 1262.5,1971.86 1313.68,1971.86 1364.86,1971.86 1416.04,1971.86 1108.95,2023.04 1160.13,2023.04 1211.32,2023.04 1262.5,2023.04 1364.86,2023.04 3834.53,2228.5
  other v6: 181.1,83.66 4622.05,83.66 96.72,132.38 265.49,132.38 4537.66,132.38 4706.43,132.38 96.72,229.82 265.49,229.82 4537.66,229.82 4706.43,229.82 181.1,278.54 4622.05,278.54 181.1,2319.88 4622.05,2319.88 96.72,2368.6 265.49,2368.6 4537.66,2368.6 4706.43,2368.6 96.72,2466.04 265.49,2466.04 4537.66,2466.04 4706.43,2466.04 181.1,2514.76 4622.05,2514.76
GND11AD_PLLD: C5.2 C534.2 L517.2 U2.D10 | length 777.1
  Top Layer w6.3: v1(2133.94,2021.89) C5.2@2133.94,2062.09 ; U2.D10@2572.04,1732.12 v2(2587.79,1747.86)
  SIGNAL 2 w4.5: v1(2133.94,2021.89) 2162.47,2021.89 2383.01,1801.35 2383.01,1707.51 2389.85,1700.67 2562.79,1700.67 2574.28,1712.15 2574.28,1734.35 v2(2587.79,1747.86)
  Bottom Layer w6.3: v1(2133.94,2021.89) L517.2@2133.94,2062.09
GND11AD_PLLM: C4.2 C533.2 L513.2 U2.C11 | length 823.2
  Top Layer w6.3: C4.2@2269.46,2224.42 v1(2314.66,2224.42) ; U2.C11@2603.53,1763.61 v2(2619.28,1779.36)
  SIGNAL 2 w4.5: v1(2314.66,2224.42) 2314.66,1929.03 2446.1,1797.6 2446.1,1772.86 2460.26,1758.7 2481.93,1758.7 2486.89,1763.66 2521.34,1763.66 2557.44,1799.76 2598.88,1799.76 v2(2619.28,1779.36)
  Bottom Layer w6.3: L513.2@2269.46,2224.42 v1(2314.66,2224.42)
GPIO_9: R23.2 R570.1 U2.K2 U9.1 U10.1 U13.2 | length 1819.7
  Top Layer w5.4: 2265.09,1532.5 2270.16,1527.43 2304.36,1527.43 U2.K2@2320.07,1543.14
  Top Layer w6.3: v2(2157.57,1534.21) R23.2@2157.57,1560.12 2203.32,1560.12 2227.13,1536.31 2261.28,1536.31 2265.09,1532.5 ; v1(2694.36,841.06) U13.2@2732.9,841.06 2763.91,841.06 2772.62,849.77 2772.62,923.79 2780.31,931.48 2780.31,943.99 ; U9.1@2731.86,1063.11 2731.86,1025.94 2780.31,977.49 2780.31,965.2 ; 2780.16,954.84 U10.1@2820.94,954.84 ; 2782.91,947.1 2782.91,962.1 ; 2780.31,943.99 2780.31,965.2 ; 2780.31,943.99 2790.91,954.59 2780.31,965.2
  SIGNAL 2 w4.5: v2(2157.57,1534.21) 2242.95,1448.83 2499.49,1448.83 2508.77,1439.55 2508.77,1319.96 2566.82,1261.91 2647.45,1261.91 2773.35,1136 2773.35,1085.2 2694.36,1006.21 v1(2694.36,841.06)
  Bottom Layer w6.3: R570.1@2694.36,812.52 v1(2694.36,841.06)
GPIO_10: R536.2 U2.K3 | length 214.1
  Top Layer w6.3: v2(2335.82,1527.39) U2.K3@2351.57,1543.14
  Bottom Layer w6.3: R536.2@2157.57,1560.12 2188.24,1560.12 2210.33,1538.03 2325.18,1538.03 v2(2335.82,1527.39)
GPIO_11: R18.2 U2.K4 | length 399
  Top Layer w5: 2274.88,1559.14 2367.06,1559.14 U2.K4@2383.06,1543.14
  Top Layer w6.3: R18.2@2035.02,1629.72 2035.02,1603.89 2043.74,1595.18 2206.31,1595.18 2242.35,1559.14 2274.88,1559.14
GPIO_12: R533.2 U2.K5 | length 443.9
  Top Layer w6.3: v2(2398.81,1527.39) U2.K5@2414.56,1543.14
  Bottom Layer w6.3: R533.2@2035.1,1629.72 2035.1,1603.15 2041.85,1596.4 2185.55,1596.4 2225.81,1556.13 2370.07,1556.13 v2(2398.81,1527.39)
GPIO_13: R22.2 U2.L1 | length 287.6
  Top Layer w6.3: R22.2@2035.02,1560.12 2035.02,1536.19 2059.57,1511.64 U2.L1@2288.57,1511.64
GPIO_14: R537.2 U2.L2 | length 361.9
  Top Layer w6.3: U2.L2@2320.07,1511.64 v2(2335.82,1495.9)
  Bottom Layer w6.3: R537.2@2035.02,1560.12 2035.02,1539.2 2054.62,1519.6 2312.11,1519.6 v2(2335.82,1495.9)
GPIO_19: R543.2 U2.M3 | length 354.9
  Top Layer w6.3: v2(2335.82,1464.4) U2.M3@2351.57,1480.15
  Bottom Layer w5.4: 2298.83,1484.73 2306.65,1484.73 2325.41,1465.96 2334.25,1465.96 v2(2335.82,1464.4)
  Bottom Layer w6.3: R543.2@2035.2,1490.69 2066.64,1459.25 2167.37,1459.25 2192.85,1484.73 2298.83,1484.73
GPIO_20: R545.2 U2.M4 | length 269.2
  Top Layer w6.3: v2(2367.31,1464.4) U2.M4@2383.06,1480.15
  Bottom Layer w5.4: 2289.29,1455.74 2296.33,1448.7 2351.61,1448.7 v2(2367.31,1464.4)
  Bottom Layer w6.3: R545.2@2160.36,1420.91 2168.9,1429.44 2168.9,1439.59 2197.31,1468 2277.03,1468 2289.29,1455.74
GPIO_22: R548.2 U2.N3 | length 234.5
  Top Layer w6.3: v2(2335.82,1432.9) U2.N3@2351.57,1448.65
  Bottom Layer w5.4: 2282.93,1409.02 2291.09,1417.18 2320.09,1417.18 v2(2335.82,1432.9)
  Bottom Layer w6.3: R548.2@2156.13,1354.31 2202.18,1400.36 2274.27,1400.36 2282.93,1409.02
GPIO_23: R547.2 U2.N4 | length 406.3
  Top Layer w6.3: v2(2367.31,1432.9) U2.N4@2383.06,1448.65
  SIGNAL 1 w4.5: v1(2035.02,1387.12) 2261.03,1387.12 2291.12,1417.2 2351.61,1417.2 v2(2367.31,1432.9)
  Bottom Layer w6.3: R547.2@2035.02,1354.31 v1(2035.02,1387.12)
GPIO_24: R542.2 U2.M5 | length 284.2
  Top Layer w6.3: v2(2398.81,1464.4) U2.M5@2414.56,1480.15
  Bottom Layer w5.4: 2323.67,1483.98 2327.55,1480.1 2383.11,1480.1 v2(2398.81,1464.4)
  Bottom Layer w6.3: R542.2@2157.06,1490.52 2161,1490.52 2172.35,1501.87 2305.79,1501.87 2323.67,1483.98
GPIO_25: R550.2 U2.P3 | length 369.3
  Top Layer w6.3: v2(2335.82,1401.41) U2.P3@2351.57,1417.16
  Bottom Layer w5.4: 2278.13,1387.41 2288.6,1387.41 2290.23,1385.78 2320.19,1385.78 v2(2335.82,1401.41)
  Bottom Layer w6.3: R550.2@2035.02,1293.01 2066.33,1324.32 2176.89,1324.32 2239.99,1387.41 2278.13,1387.41
GREEN_LED_THERM: C520.1 J3.4 R506.1 U6.93 | length 1721.7
  Top Layer w6.3: v4(3352.25,1264.94) U6.93@3352.25,1309.47 ; v1(4392.2,1979.17) J3.4@4475.2,1979.17
  SIGNAL 4 w4.5: v4(3352.25,1264.94) 3463.5,1376.19 3603.07,1376.19 3776.69,1549.82 4231.27,1549.82 4415.83,1734.37 4415.83,1955.55 v1(4392.2,1979.17)
  Bottom Layer w6.3: v1(4392.2,1979.17) C520.1@4392.2,2009.17 R506.1@4392.2,2060.73
HOLD_BOOT_H: R549.2 U510.4 | length 334.9
  Bottom Layer w6.3: R549.2@2113.89,1293.01 2113.89,1227.56 2134.62,1206.82 U510.4@2134.62,966.68
HOLD_BOOTZ: C57.1 J17.4 R571.1 SW5.1 U17.4 U510.1 | length 2384.5
  Top Layer w6.3: U17.4@569.05,257.02 569.05,229.06 v1(578.76,219.35) 601.25,219.35 612.58,208.02 J17.4@612.58,96.27 ; SW5.1@1624.53,984.67 v1(1624.53,1028.07)
  SIGNAL 4 w4.5: v1(578.76,219.35) 812.57,453.16 812.57,601.27 1171.72,960.42 1223.49,960.42 1304.09,1041.02 1372.25,1041.02 1408.95,1004.33 1600.79,1004.33 v1(1624.53,1028.07) 1655.02,997.58 1811.81,997.58 2018.82,790.57 v1(2061.56,790.57)
  Bottom Layer w6.3: U510.1@2026.36,891.87 2026.36,860.98 R571.1@2061.56,825.77 v1(2061.56,790.57)
HOST1_SPI_CLK: J10.1 R65.2 R582.2 | length 1226.8
  Top Layer w6.3: R65.2@1618.4,409.02 v1(1618.4,443.77)
  SIGNAL 1 w4.5: J10.1@501.42,439.87 551.97,490.43 1012.86,490.43 1026.23,477.07 1585.1,477.07 v1(1618.4,443.77)
  Bottom Layer w6.3: R582.2@1618.4,409.02 v1(1618.4,443.77)
HOST1_SPI_CLK_S: C625.1 J15.7 R582.1 U512.1 | length 581.6
  Top Layer w6.3: v1(1456.74,440.95) 1570.97,326.72 v1(1618.4,326.72)
  Bottom Layer w6.3: U512.1@1420.73,429.3 1445.09,429.3 v1(1456.74,440.95) ; C625.1@1557.29,55.32 J15.7@1557.29,128.74 1607.59,179.04 1607.59,315.91 v1(1618.4,326.72) R582.1@1618.4,361.77
HOST1_SPI_CSZ: J12.1 R580.2 R581.2 | length 1671
  SIGNAL 1 w4.5: J12.1@291.4,439.87 379.25,352.02 949.04,352.02 1000.19,300.87 1522.23,300.87 1630.38,409.02 v1(1768.97,409.02)
  Bottom Layer w6.3: R581.2@1677.91,409.02 R580.2@1733.91,409.02 v1(1768.97,409.02)
HOST1_SPI_CSZ_S: C623.1 J15.9 R581.1 U512.5 | length 624.4
  Top Layer w6.3: v1(1456.74,338.91) 1497.08,298.56 1649.76,298.56 v1(1677.91,326.72)
  Bottom Layer w6.3: U512.5@1420.73,350.56 1445.09,350.56 v1(1456.74,338.91) ; J15.9@1657.29,128.74 1734.71,128.74 1734.71,269.92 v1(1677.91,326.72) R581.1@1677.91,361.77
HOST1_SPI_PICO: J11.1 R583.2 R584.2 U512.2 | length 1091.7
  SIGNAL 1 w4.5: J11.1@711.44,439.87 764.86,386.45 968.42,386.45 1023.08,441.11 1404.29,441.11 1434.78,410.62 1525.16,410.62 v1(1558.9,444.36)
  Bottom Layer w6.3: U512.2@1420.73,409.61 1558.9,409.61 v1(1558.9,444.36)
HOST1_SPI_POCI: C626.1 J13.1 J15.5 U512.4 | length 977.7
  Top Layer w6.3: J13.1@921.46,439.87 1415.64,439.87 1456.74,398.77 v1(1456.74,381.89) 1407.36,332.52 1407.36,178.66 J15.5@1457.29,128.74
  Bottom Layer w6.3: U512.4@1420.73,370.24 1445.09,370.24 v1(1456.74,381.89) ; C626.1@1457.29,55.32 J15.5@1457.29,128.74
HOST2_SPI_CLK: J10.3 R567.2 | length 375.8
  SIGNAL 4 w4.5: J10.3@501.42,639.87 501.42,700.37 691.51,890.46 691.51,903.84 v1(692.16,904.5)
  Bottom Layer w6.3: R567.2@660.02,904.5 v1(692.16,904.5)
HOST2_SPI_CLK_S: R567.1 U12.12 | length 118.3
  Top Layer w6.3: v1(553.64,905.25) U12.12@612.78,905.25
  Bottom Layer w6.3: v1(553.64,905.25) R567.1@612.78,905.25
HOST2_SPI_CSZ: J12.3 R564.2 | length 584.2
  SIGNAL 4 w4.5: J12.3@291.4,639.87 411.3,639.87 655.67,884.25 655.67,919.19 v1(692.16,955.68)
  Bottom Layer w6.3: R564.2@660.02,955.68 v1(692.16,955.68)
HOST2_SPI_CSZ_S: R564.1 U12.11 | length 128.9
  Top Layer w6.3: v1(553.64,956.43) 579.23,930.84 U12.11@612.78,930.84
  Bottom Layer w6.3: v1(553.64,956.43) R564.1@612.78,956.43
HOST2_SPI_PICO: J11.3 R568.2 | length 230.5
  Top Layer w6.3: J11.3@711.01,639.87 711.01,793.54 724.81,807.34 v1(724.81,834.55)
  Bottom Layer w6.3: v1(724.81,834.55) R568.2@754.95,834.55
HOST2_SPI_PICO_S: R568.1 U12.14 | length 271.6
  Top Layer w6.3: v1(553.64,868.49) 568.07,854.06 U12.14@612.78,854.06
  Bottom Layer w6.3: v1(553.64,868.49) 703.38,868.49 715.93,881.04 R568.1@754.95,881.04
HOST2_SPI_POCI: J13.3 U12.13 | length 526.6
  Top Layer w6.3: U12.13@612.78,879.65 732.72,879.65 753.31,859.06 753.31,795.33 735.45,777.47 735.45,699.78 795.36,639.87 J13.3@921.46,639.87
HOST_I2C_SCL: C621.1 J17.2 R593.1 U2.M15 U7.4 U16.2 | length 4586.2
  Top Layer w6.3: U16.2@836.99,274.94 v1(836.99,307.34) ; v1(1252.11,1219.91) U7.4@1288.48,1219.91 ; U2.M15@2729.52,1480.15 v2(2745.27,1464.4)
  SIGNAL 3 w4.5: v1(1252.11,1219.91) 1230.46,1241.56 1180.34,1241.56 1138.38,1199.61 1138.38,963.86 836.99,662.46 v1(836.99,307.34) 836.99,306.34 857.76,285.56 965.69,285.56 1174.96,494.83 1174.96,553.18 1250.67,628.9 1300.53,628.9 1371.83,700.2 1430.25,700.2 1500.35,630.1 2472.9,630.1 2654.42,811.62 2702.43,811.62 2761.22,870.41 2761.22,1096.18 2927.79,1262.75 2927.79,1420.08 2905.21,1442.66 2878.39,1442.66 2868.72,1432.98 2833.61,1432.98 2817.89,1448.7 2801.76,1448.7 2792.56,1457.9 2792.56,1471.27 2783.7,1480.12 2760.99,1480.12 v2(2745.27,1464.4)
  Bottom Layer w6.3: J17.2@812.58,96.27 812.58,194.05 C621.1@821.11,202.58 R593.1@821.11,259.94 821.11,291.46 v1(836.99,307.34)
HOST_I2C_SDA: C620.1 J17.1 R592.1 U2.L15 U7.5 U16.1 | length 4355.2
  Top Layer w6.3: U16.1@888.17,274.94 v1(888.17,307.34) ; U7.5@1162.49,1219.91 v1(1193.86,1219.91) ; U2.L15@2729.52,1511.64 v2(2745.27,1495.9)
  SIGNAL 3 w4.5: v1(1193.86,1219.91) 1154.51,1180.56 1154.51,955.03 853.92,654.44 853.92,341.59 v1(888.17,307.34) 966.95,307.34 1151.49,491.88 1151.49,550.06 1250.2,648.77 1292.28,648.77 1363.58,720.07 1438.48,720.07 1510.58,647.97 2458.03,647.97 2691.85,881.79 2691.85,1118.5 2730.79,1157.45 2799.69,1157.45 2871.45,1229.2 2871.45,1391.2 2861.06,1401.58 2838.44,1401.58 2822.82,1417.2 2801.76,1417.2 2792.56,1426.4 2792.56,1439.77 2783.7,1448.63 2738.84,1448.63 2729.54,1457.92 2729.54,1480.17 v2(2745.27,1495.9)
  Bottom Layer w6.3: v1@888.17,306.34 904.05,290.46 R592.1@904.05,259.94 C620.1@904.05,202.58 912.58,194.05 J17.1@912.58,96.27
HOST_IF_SEL: R37.1 U2.N1 | length 361.2
  Top Layer w6.3: R37.1@2035.02,1293.01 2035.02,1314.45 2045.18,1324.61 2178.26,1324.61 2208.72,1355.07 2208.72,1376.56 2239.13,1406.97 2239.13,1437.75 2250.04,1448.65 U2.N1@2288.57,1448.65
HOST_IRQ: C58.1 J17.5 R39.1 R551.2 U4.3 U15.2 U17.1 | length 5091.3
  Top Layer w6.3: v1(264.99,1408.69) 264.99,1421.08 270.46,1426.55 U4.3@300.88,1426.55 ; v1(486.94,257.02) U17.1@510,257.02 510,183.56 C58.1@511.75,181.81 ; J17.5@512.58,95.27 C58.1@512.58,181.81 ; U15.2@1341.6,674 v1(1380.28,674) ; R39.1@2986,1267.65 v1(3021.81,1267.65)
  SIGNAL 3 w4.5: v1(486.94,257.02) 486.94,228.63 557.8,157.77 972.71,157.77 1317.3,502.37 1317.3,610.8 v1@1380.28,673.78 ; v1(1380.28,674) 1428.07,674 1489.85,612.22 2629.62,612.22 2653.81,636.41 2787.17,636.41 3021.81,871.05 v1(3021.81,1267.65)
  Bottom Layer w6.3: v1(264.99,1408.69) 216.58,1360.28 216.58,421.66 381.22,257.02 v1(486.94,257.02) ; R551.2@2986,1267.65 v1(3021.81,1267.65)
HOST_IRQ_S: R39.2 U2.N15 | length 353.8
  Top Layer w6.3: U2.N15@2729.52,1448.65 v2(2745.27,1432.9) ; v1(2902.94,1267.65) R39.2@2938.75,1267.65
  Bottom Layer w5: v2(2745.27,1432.9) 2760.97,1417.2 2815.91,1417.2 2827.8,1405.31 2827.8,1394.81
  Bottom Layer w6.3: 2827.8,1394.81 2827.8,1286.56 2846.71,1267.65 v1(2902.94,1267.65)
HOST_SPI_CLK: J10.2 U2.U16 | length 3112.1
  Top Layer w6.3: U2.U16@2761.01,1322.56 v2(2776.68,1306.9)
  SIGNAL 2 w4.5: J10.2@501.42,539.87 501.42,538.24 651.49,388.16 976.49,388.16 1052.92,311.73 1498.44,311.73 1543.02,356.31 1784.4,356.31 1807.4,333.31 2002.77,333.31 2463.68,794.22 2718.02,794.22 2780.26,856.46 2780.26,940.58 2803.26,963.58 2803.26,1236.24 2803.26,1253.57 2776.68,1280.16 v2(2776.68,1306.9)
HOST_SPI_CSZ: J12.2 U2.T16 | length 3462.1
  Top Layer w6.3: U2.T16@2761.01,1354.16 v2(2776.76,1338.42)
  SIGNAL 2 w4.5: J12.2@291.4,539.87 472.59,358.68 954.09,358.68 1023.52,289.25 1707.01,289.25 1726.41,269.86 1995.59,269.86 2434.15,708.41 2725.36,708.41 2826.22,809.27 2826.22,1225.08 2836.45,1235.31 2836.45,1271.35 2818.56,1289.23 2798.69,1289.23 2792.26,1295.66 2792.26,1322.92 v2(2776.76,1338.42)
HOST_SPI_MODE: R38.1 TP9.1 U2.P2 | length 1689.9
  Top Layer w5.4: 2260.36,1392.58 2270.61,1392.58 2279.51,1401.48 v2(2304.12,1401.48)
  Top Layer w6.3: R38.1@2161.13,1293.01 2188.06,1293.01 2232.41,1337.36 2232.41,1371.32 2253.68,1392.58 2260.36,1392.58 ; v2@2304.26,1401.48 U2.P2@2319.93,1417.16
  SIGNAL 2 w4.5: TP9.1@1387.48,539.32 1387.48,617.63 1355.29,649.81 1355.29,779.42 1565.27,989.4 1869.34,989.4 2281.42,1401.48 v2(2304.12,1401.48)
HOST_SPI_PICO: J11.2 U2.R16 | length 2893.4
  Top Layer w6.3: U2.R16@2761.01,1385.66 v2(2776.76,1369.91)
  SIGNAL 2 w4.5: J11.2@711.44,539.87 762.17,489.14 986.38,489.14 1032.76,442.76 1380.09,442.76 1407.73,415.12 1714.42,415.12 1737.84,438.54 1808.51,438.54 1850.82,396.23 2007.32,396.23 2318.99,707.9 2318.99,729.25 2397.69,807.96 2707.49,807.96 2762.26,862.73 2762.26,949.3 2788.3,975.33 2788.3,1236.24 2788.3,1250.78 2761.18,1277.9 2761.18,1354.32 v2(2776.76,1369.91)
HOST_SPI_POCI: J13.2 R555.1 | length 2201.9
  SIGNAL 2 w4.5: J13.2@921.46,539.87 977.18,539.87 1045.4,471.66 1529.11,471.66 1536.74,479.29 1827.01,479.29 1843.97,462.33 1938.43,462.33 1964.87,488.77 1964.87,538.64 2414.3,988.07 2566.98,988.07 2709.43,1130.52 v1(2748.23,1130.52)
  Bottom Layer w6.3: R555.1@2717.57,1130.52 v1(2748.23,1130.52)
HOST_SPI_POCI_S: R555.2 U2.P15 | length 298.8
  Top Layer w6.3: U2.P15@2729.52,1417.16 v2(2745.27,1401.41)
  Bottom Layer w5.4: 2691.96,1314.32 2697.51,1319.87 2697.51,1375.86 2707.32,1385.66 2729.52,1385.66 v2(2745.27,1401.41)
  Bottom Layer w6.3: 2691.96,1314.32 2682.35,1304.7 2682.35,1251.12 2717.02,1216.45 R555.2@2717.02,1178.31
HOTPLUGDETECT: C6.1 J4.19 R2.1 | length 164.3
  Top Layer w6.3: J4.19@451.18,2037.85 508.06,2037.85 520.35,2050.14 520.35,2061.16 533.82,2074.62 R2.1@593.75,2074.62
HS_A_CLK_N: J1.18 U2.A15 | length 1388.3
  Top Layer w5.4: U2.A15@2729.52,1826.6 2729.52,1864.1 2763.33,1897.91 3013.78,1897.91 3050.02,1861.67 3126.11,1861.67 3193.25,1928.81 3193.25,2022.63 3225.47,2054.85 3304.86,2054.85 3330.81,2080.79 3330.81,2170.69 3354.27,2194.16 3542.45,2194.16 3695.46,2347.17 3695.46,2369.87 3694.02,2371.32 J1.18@3694.02,2393.7
HS_A_CLK_P: J1.17 U2.B15 | length 1426.8
  Top Layer w5.4: U2.B15@2729.52,1795.11 2745.27,1810.86 2745.27,1836.47 2746.32,1837.52 2746.32,1857.14 2770.29,1881.11 2879.39,1881.11 3006.82,1881.11 3043.06,1844.87 3133.07,1844.87 3210.05,1921.85 3210.05,2015.67 3232.43,2038.05 3311.82,2038.05 3347.61,2073.83 3347.61,2163.74 3361.23,2177.36 3549.41,2177.36 3712.26,2340.21 3712.26,2369.87 3713.7,2371.32 J1.17@3713.7,2393.7
HS_A_WDATA0_N: J1.28 U2.A11 | length 1340.8
  Top Layer w5.4: U2.A11@2603.53,1826.6 2603.53,1926.14 2694.78,2017.39 2968.98,2017.39 2994.3,2042.71 3045.45,2042.71 3057.23,2054.49 3057.23,2149.76 3105.69,2198.22 3185.01,2198.22 3192.84,2206.05 3192.84,2247.04 3183.51,2256.38 3183.51,2299.52 3202.19,2318.2 3245.64,2318.2 3251.72,2324.28 3477.28,2324.28 3498.61,2345.61 3498.61,2369.87 3497.17,2371.32 J1.28@3497.17,2393.7
HS_A_WDATA0_P: J1.27 U2.B11 | length 1379.3
  Top Layer w5.4: U2.B11@2603.53,1795.11 2619.28,1810.86 2619.28,1836.47 2620.33,1837.52 2620.33,1919.18 2701.74,2000.59 2975.93,2000.59 3001.26,2025.91 3052.41,2025.91 3074.03,2047.53 3074.03,2142.8 3112.65,2181.42 3191.97,2181.42 3209.64,2199.09 3209.64,2254 3200.31,2263.34 3200.31,2292.56 3209.14,2301.4 3252.6,2301.4 3258.68,2307.48 3484.24,2307.48 3515.41,2338.65 3515.41,2369.87 3516.85,2371.32 J1.27@3516.85,2393.7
